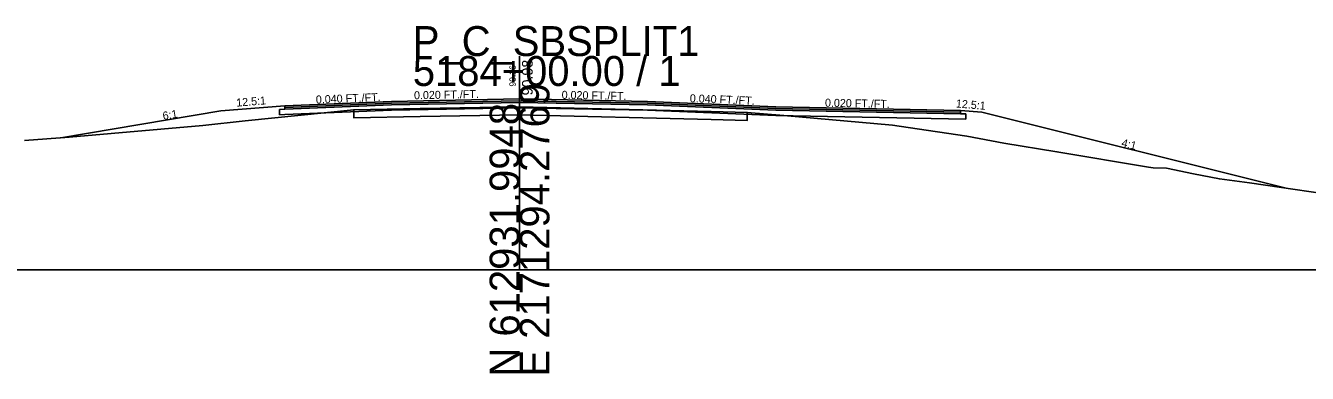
# Model space of a CAD drawing. Extents: x -26 to 1303, y -3010 to 12023.
# Drawn here: x 103.7 to 223.8, y 6490.3 to 6522.8 of the extents above; entities that cross this region are included whole.
import ezdxf

# ---------------------------------------------------------------- set-up
doc = ezdxf.new("R2010")
doc.units = 0
for name, color, linetype in [('RD_GPK_XS_Cell', 7, 'Continuous'), ('RD_XS_Base', 7, 'Continuous'), ('RD_XS_ExGround', 7, 'Continuous'), ('RD_XS_ExPaveRet', 7, 'Continuous'), ('RD_XS_Greenside', 7, 'Continuous'), ('RD_XS_Pave', 7, 'Continuous'), ('RD_XS_PaveOvlay_CP', 7, 'Continuous'), ('RD_XS_TieSlope', 7, 'Continuous'), ('RD_XS_TX_Elev_EX', 7, 'Continuous'), ('RD_XS_TX_Elev_PR', 7, 'Continuous'), ('RD_XS_TX_ShdSlope', 7, 'Continuous'), ('RD_XS_TX_Slope', 7, 'Continuous')]:
    doc.layers.add(name, color=color, linetype=linetype)

msp = doc.modelspace()

# ---------------------------------------------------------------- linework, layer by layer
at = {"layer": 'RD_GPK_XS_Cell'}
for p, q in [((150, 6500), (150, 6520)), ((0, 6500), (150, 6500)), ((150, 6500), (300, 6500))]:
    msp.add_line(p, q, dxfattribs=at)
at = {"layer": 'RD_XS_Base'}
for p, q in [((138, 6515.42), (150, 6515.66)), ((150, 6515.66), (150, 6515.82)), ((150, 6515.82), (150, 6515.16)), ((150, 6515.66), (150, 6515.66)), ((162, 6515.42), (150, 6515.66)), ((150, 6515.66), (150, 6515.66)), ((150, 6515.66), (150, 6515.16)), ((127.5, 6515), (128, 6515.02)), ((127.5, 6514.5), (127.5, 6515)), ((127.5, 6515), (127.5, 6515)), ((128, 6514.52), (127.5, 6514.5)), ((127.5, 6514.5), (127.5, 6514.5)), ((127.5, 6514.5), (127.5, 6514.5)), ((128, 6515.02), (138, 6515.42)), ((128, 6515.02), (128, 6515.02)), ((138, 6514.92), (128, 6514.52)), ((128, 6514.52), (128, 6514.52)), ((136, 6515.34), (136, 6515.34)), ((136, 6514.84), (136, 6514.84)), ((150, 6515.16), (138, 6514.92)), ((150, 6515.16), (150, 6515.16)), ((150, 6515.16), (162, 6514.92)), ((150, 6515.16), (150, 6515.16)), ((174, 6514.94), (162, 6515.42)), ((162, 6515.42), (162, 6515.42)), ((162, 6514.92), (162, 6514.92)), ((162, 6514.92), (174, 6514.44)), ((191.32, 6514.59), (174, 6514.94)), ((174, 6514.94), (174, 6514.94)), ((191.82, 6514.58), (191.32, 6514.59)), ((191.32, 6514.59), (191.32, 6514.59)), ((191.82, 6514.08), (191.82, 6514.58)), ((191.82, 6514.58), (191.82, 6514.58)), ((174, 6514.44), (174, 6514.44)), ((174, 6514.44), (191.82, 6514.08)), ((191.82, 6514.08), (191.82, 6514.08)), ((191.82, 6514.08), (191.82, 6514.08))]:
    msp.add_line(p, q, dxfattribs=at)
at = {"layer": 'RD_XS_ExGround'}
msp.add_lwpolyline([(103.61, 6512.09), (107.8, 6512.42), (120.34, 6513.5), (124.28, 6513.94), (134.46, 6514.98), (140.68, 6515.09), (150, 6515.26), (167.96, 6514.81), (171.34, 6514.73), (174.75, 6514.45), (184.93, 6513.52), (186.41, 6513.3), (191.91, 6512.5), (195.37, 6511.86), (200.35, 6511.04), (208.94, 6509.6), (209.15, 6509.57), (209.37, 6509.55), (210.61, 6509.51), (213.13, 6508.99), (215.57, 6508.5), (218.38, 6508.12), (222.68, 6507.5), (227.78, 6506.77)], dxfattribs=at)
at = {"layer": 'RD_XS_ExPaveRet'}
for points in [[(171.34, 6514.73), (171.34, 6514.73), (171.34, 6513.98), (171.34, 6513.98), (171.34, 6513.98), (167.96, 6514.06), (167.96, 6514.06), (150, 6514.51), (150, 6514.51), (140.68, 6514.34), (140.68, 6514.34), (134.46, 6514.23), (134.46, 6514.23), (134.46, 6514.98), (140.68, 6515.09), (140.68, 6515.09), (150, 6515.26), (150, 6515.26), (167.96, 6514.81), (167.96, 6514.81), (171.34, 6514.73)], [(167.96, 6514.81), (150, 6515.26), (140.68, 6515.09), (134.46, 6514.98), (134.46, 6514.23), (140.68, 6514.34), (150, 6514.51), (167.96, 6514.06), (171.34, 6513.98), (171.34, 6514.73), (167.96, 6514.81)]]:
    msp.add_lwpolyline(points, dxfattribs=at)
at = {"layer": 'RD_XS_Greenside'}
for p, q in [((122, 6514.86), (107.01, 6512.36)), ((193.32, 6514.75), (221.82, 6507.63))]:
    msp.add_line(p, q, dxfattribs=at)
at = {"layer": 'RD_XS_Pave'}
for p, q in [((138, 6515.74), (128, 6515.34)), ((136, 6515.66), (136, 6515.66)), ((150, 6515.98), (138, 6515.74)), ((150, 6515.82), (138, 6515.58)), ((138, 6515.58), (150, 6515.82)), ((138, 6515.42), (150, 6515.66)), ((162, 6515.74), (150, 6515.98)), ((150, 6515.66), (150, 6515.82)), ((150, 6515.82), (162, 6515.58)), ((162, 6515.58), (150, 6515.82)), ((150, 6515.82), (150, 6515.82)), ((150, 6515.82), (150, 6515.66)), ((150, 6515.66), (150, 6515.66)), ((150, 6515.66), (150, 6515.66)), ((150, 6515.66), (150, 6515.66)), ((150, 6515.66), (162, 6515.42)), ((174, 6515.26), (162, 6515.74)), ((162, 6515.74), (162, 6515.74)), ((138, 6515.58), (128, 6515.18)), ((128, 6515.18), (138, 6515.58)), ((128, 6515.02), (138, 6515.42)), ((128, 6515.34), (128, 6515.34)), ((128, 6515.34), (128, 6515.18)), ((128, 6515.18), (128, 6515.18)), ((128, 6515.18), (128, 6515.02)), ((128, 6515.18), (128, 6515.18)), ((128, 6515.18), (128, 6515.18)), ((128, 6515.02), (128, 6515.02)), ((128, 6515.02), (128, 6515.02)), ((136, 6515.5), (136, 6515.5)), ((136, 6515.5), (136, 6515.5)), ((136, 6515.34), (136, 6515.34)), ((162, 6515.58), (162, 6515.58)), ((162, 6515.58), (174, 6515.1)), ((174, 6515.1), (162, 6515.58)), ((162, 6515.58), (162, 6515.58)), ((162, 6515.42), (162, 6515.42)), ((162, 6515.42), (174, 6514.94)), ((191.32, 6514.91), (174, 6515.26)), ((174, 6515.26), (174, 6515.26)), ((174, 6515.1), (174, 6515.1)), ((174, 6515.1), (191.32, 6514.75)), ((191.32, 6514.75), (174, 6515.1)), ((174, 6515.1), (174, 6515.1)), ((174, 6514.94), (174, 6514.94)), ((174, 6514.94), (191.32, 6514.59)), ((191.32, 6514.75), (191.32, 6514.91)), ((191.32, 6514.91), (191.32, 6514.91)), ((191.32, 6514.75), (191.32, 6514.75)), ((191.32, 6514.75), (191.32, 6514.75)), ((191.32, 6514.59), (191.32, 6514.75)), ((191.32, 6514.75), (191.32, 6514.75)), ((191.32, 6514.59), (191.32, 6514.59)), ((191.32, 6514.59), (191.32, 6514.59))]:
    msp.add_line(p, q, dxfattribs=at)
at = {"layer": 'RD_XS_PaveOvlay_CP'}
for p, q in [((138, 6515.74), (128, 6515.34)), ((136, 6515.66), (136, 6515.66)), ((150, 6515.98), (138, 6515.74)), ((162, 6515.74), (150, 6515.98)), ((174, 6515.26), (162, 6515.74)), ((162, 6515.74), (162, 6515.74)), ((128, 6515.34), (128, 6515.34)), ((191.32, 6514.91), (174, 6515.26)), ((174, 6515.26), (174, 6515.26)), ((191.32, 6514.91), (191.32, 6514.91))]:
    msp.add_line(p, q, dxfattribs=at)
at = {"layer": 'RD_XS_TieSlope'}
for p, q in [((128, 6515.34), (122, 6514.86)), ((191.32, 6514.91), (193.32, 6514.75))]:
    msp.add_line(p, q, dxfattribs=at)

# ---------------------------------------------------------------- texts
at = {"layer": 'RD_GPK_XS_Cell'}
for s, p in [('P_C_SBSPLIT1', (140, 6520)), ('5184+00.00 / 1', (140, 6517.2))]:
    msp.add_text(s, height=2.8, dxfattribs=at).set_placement(p)
for s, p in [('E 2171294.2769', (152.8, 6490)), ('N 612931.9948', (150, 6490))]:
    msp.add_text(s, height=2.8, rotation=90, dxfattribs=at).set_placement(p)
at = {"layer": 'RD_XS_TX_Elev_EX'}
msp.add_text('90.26', height=0.6, rotation=90, dxfattribs=at).set_placement((149.65, 6517.14))
at = {"layer": 'RD_XS_TX_Elev_PR'}
msp.add_text('90.98', height=1, rotation=90, dxfattribs=at).set_placement((151.23, 6516.31))
at = {"layer": 'RD_XS_TX_ShdSlope'}
for rotation, p in [(4.5739, (123.49, 6515.26)), (355.4261, (190.86, 6515.19))]:
    msp.add_text('12.5:1', height=0.75, rotation=rotation, dxfattribs=at).set_placement(p)
at = {"layer": 'RD_XS_TX_Slope'}
for s, rotation, p in [('0.040 FT./FT.', 2.2906, (130.93, 6515.55)), ('0.020 FT./FT.', 1.1458, (140.12, 6515.95)), ('0.020 FT./FT.', 358.8542, (153.94, 6516)), ('0.040 FT./FT.', 357.7094, (165.94, 6515.68)), ('0.020 FT./FT.', 358.8542, (178.61, 6515.26)), ('6:1', 9.4623, (116.63, 6514.02)), ('4:1', 345.9638, (206.34, 6511.55))]:
    msp.add_text(s, height=0.75, rotation=rotation, dxfattribs=at).set_placement(p)

doc.saveas('drawing.dxf')
